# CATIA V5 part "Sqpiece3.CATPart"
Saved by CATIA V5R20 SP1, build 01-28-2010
Part number: Sqpiece3
Publications: "Plan.2", "Droite.5", "Droite.3", "Plan.1", "Droite.4", "LongueurAB", "LongueurAE"
Bounding box of the stored display mesh (mm): x 0 to 134.35, y -134.35 to 80, z -20 to 20
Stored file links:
  C:\Users\RENARD Simon\Documents\Cours IFMA\2ème année\IAO\Sqpiece3.CATPart
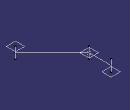
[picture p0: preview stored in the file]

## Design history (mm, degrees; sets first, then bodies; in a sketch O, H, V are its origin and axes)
Parameters
  LongueurAB = 190 mm
  LongueurAE = 80 mm
Body1 (main body)
  Point1: (0, 0, 0)
  Line1: type PtDir, RefPoint Point1, Direction zx-plane, Start 0, End 80 {= LongueurAE}
  Line2: type Angle, RefPoint Point1, Curve Line1, Support xy-plane, Start 0, End 190 {= LongueurAB}, Angle -135
  Line3: type PtDir, RefPoint vertex of Line1, Direction xy-plane, Start -20, End 20
  Line4: type PtDir, RefPoint Point1, Direction xy-plane, Start -20, End 20
  Line5: type PtDir, RefPoint vertex of Line2, Direction xy-plane, Start -20, End 20
  Plane1: type OffsetPt, RefPlane xy-plane, RefPoint vertex of Line3
  Plane2: type OffsetPt, RefPlane xy-plane, RefPoint vertex of Line5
